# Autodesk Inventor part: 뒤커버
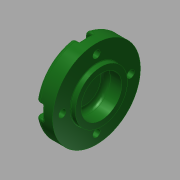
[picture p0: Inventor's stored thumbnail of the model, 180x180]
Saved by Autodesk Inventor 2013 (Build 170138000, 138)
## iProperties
Created: 2015-11
Part Number: 뒤커버
Material: 알루미늄 6061
Document SubType Name: Modeling
Designer: mduedu
Density: 1 g/cm^3
Author: mduedu
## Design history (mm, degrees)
sketch "스케치1"
  geometry: L1 (-7, 0)-(7, 0); L2 (-7, 0)-(-7, 27); L3 (-7, 27)-(4, 27); L4 (4, 27)-(4, 16); L5 (4, 16)-(7, 16); L6 (7, 16)-(7, 0); 2 further points
  constraints: 12 end point, 3 perpendicular, 2 parallel, 1 coincident, 1 horizontal, 1 midpoint
  dimensions: "d0" = 14 distance of L1.start L1.end; "d1" = 54 diameter of L3 L1; "d2" = 3 distance of L4.end L5.end; "d3" = 32 diameter of L5 L1
revolve "회전1" sketch "스케치1" stored, may be unused: angle "d4" = 90 deg
hole "구멍1" diameter "d7" = 25; stored, may be unused: countersink angle "d11" = 90 deg, drill point angle "d13" = 0 deg; dims "d8" = 6, "d9" = 4, "d10" = 2, "d12" = 10, "d66" = 10, "d67" = 10
fillet "모깎기2" dims "d36" = 3
fillet "모깎기3" dims "d37" = 3
fillet "모깎기4" dims "d38" = 0.3
sketch "스케치3" dims "d61" = 42
  geometry: C1 r 27 at (0, 0) reference; 2 further points
  constraints: 2 vertical alignment, 1 coincident, 2 other
hole "구멍4" sketch "스케치3" at (0, 21) diameter "d44" = 4.5; stored, may be unused: countersink angle "d48" = 90 deg, drill point angle "d50" = 0 deg; dims "d45" = 6, "d46" = 8, "d47" = 4.6, "d49" = 8
sketch "스케치4"
  geometry: L1 (-4, 5.702)-(-4, 0); L2 (4, 5.702)-(4, 0); A1 r 27 centre (0, -21) between (-4, 5.702) and (4, 5.702) reference; A2 r 4 centre (0, 0) between (-2.824, 2.833) and (2.824, 2.833) reference
  constraints: 4 end point, 4 point on circle, 2 tangent, 2 vertical
extrude "돌출1" cut sketch "스케치4" stored distance "d51" = 0; taper "d52" = 0 deg
fillet "모깎기5" dims "d56" = 0.3
fillet "모깎기6" dims "d57" = 1
node "솔리드1"
pattern_circular "원형 패턴2" dims angle "d64" = 360 deg
pattern_circular "원형 패턴1" dims angle "d54" = 360 deg
